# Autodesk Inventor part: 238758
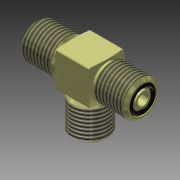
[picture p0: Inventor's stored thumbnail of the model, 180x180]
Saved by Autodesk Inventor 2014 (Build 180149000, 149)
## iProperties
Shininess: 20.0
Length Units: 11272
Angle Units: 11279
Time Units: 11290
Mass Units: 11286
Length Display Precision: 3
Angle Display Precision: 2
Company: Autodesk, Inc.
Created: 2002-06
Part Number: 238758
Material: Steel, Mild A-36
Description: Fitting; TE-C9C9C94-S
Document SubType Name: Modeling
Designer: Autodesk, Inc.
Density: 1 g/cm^3
Appearance: Yellow Zinc
Density: 0.0
Volumn: 0.0
Area: 0.0
PropertySet Name: Model Information
Control State: 0
Master: False
Checked Out: False
Last Check In By: JT
Last Check In Date: 2003-06-20
Title: Fitting; TE-C9C9C94-S
Author: Autodesk, Inc.
Comments: -
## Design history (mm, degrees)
sketch "Sketch1"
  geometry: L1 (-7.137, -7.137)-(7.137, -7.137); L2 (7.137, -7.137)-(7.137, 7.137); L3 (7.137, 7.137)-(-7.137, 7.137); L4 (-7.137, 7.137)-(-7.137, -7.137); L5 (-7.137, -7.137)-(7.137, 7.137); 2 further points
  constraints: 10 end point, 2 parallel, 1 coincident, 1 horizontal, 1 midpoint, 1 perpendicular
  dimensions: "d3" = 14.2748 distance of L2.end L3.end (= Body_Size); "d4" = 14.2748 distance of L3.end L1.start (= Body_Size)
extrude "Extrusion2" new body sketch "Sketch1" stored distance "d5" = 14.2748 (= Body_Size); taper "d6" = 0 deg
workplane "Work Plane1"
sketch "Sketch2"
  geometry: L1 (-7.137, 10.094)-(-7.137, 0) reference; L2 (7.137, 0)-(7.137, 10.094) reference; L3 (-7.137, 7.137)-(-6.616, 10.094); L4 (7.137, 7.137)-(6.616, 10.094); L5 (7.137, 7.137)-(-7.137, 7.137); L6 (-9.992, 0)-(9.992, 0) reference; L7 (-7.137, 10.094)-(-6.616, 10.094); L8 (6.616, 10.094)-(7.137, 10.094)
  constraints: 10 end point, 2 parallel, 2 point on line, 1 horizontal
  dimensions: "d7" = 14.2748 diameter of L5 L6 (= Body_Size); "d8" = 10 deg angle of L3 L1; "d9" = 10 deg angle of L2 L4 (= d8)
revolve "Revolution1" sketch "Sketch2" stored, may be unused: angle "d10" = 90 deg
fillet "Fillet1" dims "d11" = 0.762
sketch "Sketch3"
  geometry: L1 (-7.137, 7.137)-(-7.137, 0) reference; L2 (-7.137, 0)-(-7.137, -7.137) reference; L3 (0, 0)-(-46.922, 0); L4 (0, 0)-(49.071, 0); L5 (0, 0)-(0, -39.416); L6 (6.708, -7.137)-(-6.708, -7.137) reference; L7 (7.137, 0)-(7.137, 7.137) reference; L8 (7.137, -7.137)-(7.137, 0) reference; L9 (-7.137, 6.134)-(-7.899, 6.134); L10 (-7.899, 6.134)-(-8.909, 7.144); L11 (-8.909, 7.144)-(-20.58, 7.144); L12 (-20.58, 7.144)-(-21.59, 6.134); L13 (-21.59, 6.134)-(-21.59, 5.499); L14 (-21.59, 5.499)-(-20.244, 5.499); L15 (-20.244, 5.499)-(-20.244, 3.086); L16 (-20.244, 3.086)-(-21.59, 3.086); L17 (-21.59, 3.086)-(-21.59, 2.184); L18 (-21.59, 2.184)-(-7.137, 2.184); L19 (7.137, 6.134)-(7.899, 6.134); L20 (7.899, 6.134)-(8.909, 7.144); L21 (8.909, 7.144)-(20.58, 7.144); L22 (20.58, 7.144)-(21.59, 6.134); L23 (21.59, 6.134)-(21.59, 5.499); L24 (21.59, 5.499)-(20.244, 5.499); L25 (20.244, 5.499)-(20.244, 3.086); L26 (20.244, 3.086)-(21.59, 3.086); L27 (21.59, 3.086)-(21.59, 2.184); L28 (21.59, 2.184)-(7.137, 2.184); L29 (-6.134, -7.137)-(-6.134, -7.899); L30 (-6.134, -7.899)-(-7.144, -8.909); L31 (-7.144, -8.909)-(-7.144, -20.58); L32 (-7.144, -20.58)-(-6.134, -21.59); L33 (-6.134, -21.59)-(-5.499, -21.59); L34 (-5.499, -21.59)-(-5.499, -20.244); L35 (-5.499, -20.244)-(-3.086, -20.244); L36 (-3.086, -20.244)-(-3.086, -21.59); L37 (-3.086, -21.59)-(-2.184, -21.59); L38 (-2.184, -21.59)-(-2.184, -7.137); C1 r 0.787 at (-21.031, 4.61); C2 r 0.787 at (-4.61, -21.031); C3 r 0.787 at (21.031, 4.61)
  constraints: 66 end point, 14 perpendicular, 13 parallel, 6 point on line, 5 collinear, 3 centre point, 2 horizontal alignment, 1 vertical alignment
  dimensions: "d12" = 14.2875 diameter of L11 L3 (= Male2_Face_Seal_Thread_OD); "d13" = 12.2682 diameter of L12.end L3 (= Male2_Face_Seal_Lip); "d14" = 45 deg angle of L11 L12; "d15" = 10.9982 diameter of L14 L3 (= Male2_Face_Seal_Groove_Dia); "d16" = 1.3462 distance from line of L15.end L13; "d17" = 4.3688 diameter of L18 L3 (= Male2_Face_Seal_ID); "d18" = 2.413 distance between parallel lines of L16 L14; "d19" = 21.59 distance from line of L13 L3.start (= Male1_M); "d20" = 0.762 distance of L9.start L9.end (= Male2_Face_Seal_Undercut_Length_H); "d21" = 21.59 distance from line of L33 L3.start (= Male1_M); "d22" = 14.2875 diameter of L31 L5 (= Male2_Face_Seal_Thread_OD); "d23" = 45 deg angle of L31 L32; "d24" = 12.2682 diameter of L32.end L5 (= Male2_Face_Seal_Lip); "d25" = 0.762 distance of L29.start L29.end (= Male2_Face_Seal_Undercut_Length_H); "d26" = 10.9982 diameter of L34 L5 (= Male2_Face_Seal_Groove_Dia); "d27" = 2.413 distance between parallel lines of L36 L34; "d28" = 1.3462 distance between parallel lines of L35 L37; "d29" = 4.3688 diameter of L38 L5 (= Male2_Face_Seal_ID); "d30" = 21.59 distance from line of L27 L3.start (= Male2_M); "d31" = 14.2875 diameter of L21 L4 (= Male1_Face_Seal_Thread_OD); "d32" = 10.9982 diameter of L24 L4 (= Male1_Face_Seal_Groove_Dia); "d33" = 2.413 distance between parallel lines of L26 L24; "d34" = 1.3462 distance between parallel lines of L27 L25; "d35" = 0.762 distance of L19.start L19.end (= Male1_Face_Seal_Undercut_Length_H); "d36" = 45 deg angle of L21 L22; "d37" = 12.2682 diameter of L22.end L4 (= Male1_Face_Seal_Lip); "d38" = 4.3688 diameter of L28 L4 (= Male2_Face_Seal_ID); "d48" = 1.5748 diameter of C3 (= Male1_Face_Seal_Seal); "d49" = 1.5748 diameter of C1 (= Male2_Face_Seal_Seal); "d50" = 1.5748 diameter of C2 (= Male2_Face_Seal_Seal); "d53" = 21.0312 horizontal distance of L3.start C1.centre (computed from Male2_M, Male2_Face_Seal_Seal); "d54" = 21.0312 horizontal distance of L3.start C3.centre (computed from Male1_M, Male1_Face_Seal_Seal); "d55" = 21.0312 vertical distance of C2.centre L3.start (computed from Male2_M, Male2_Face_Seal_Seal); "d67" = 7.6454 dimension on C1 L3 (= Male2_Oring_Dia); "d68" = 7.6454 dimension on C3 L4 (= Male1_Oring_Dia); "d69" = 7.6454 dimension on C2 L5 (= Male2_Oring_Dia)
revolve "Male FS1" stored, may be unused: angle "d39" = 90 deg
revolve "Oring FS1" stored, may be unused: angle "d58" = 90 deg
revolve "Male FS2" stored, may be unused: angle "d40" = 90 deg
revolve "Oring FS2" stored, may be unused: angle "d59" = 90 deg
revolve "Male FS3" stored, may be unused: angle "d41" = 90 deg
revolve "Oring FS3" stored, may be unused: angle "d60" = 90 deg
feature "Male Thd FS1" dims "d42" = 25.4, "d43" = 0
feature "Male Thd FS2" dims "d44" = 25.4, "d45" = 0
feature "Male Thd FS3" dims "d46" = 25.4, "d47" = 0
sketch "Sketch4"
  geometry: C1 r 2.184 at (0, 0); 1 further point
  constraints: 1 centre point, 1 coincident
  dimensions: "d138" = 4.3688 diameter of C1 (derived)
extrude "FS1 Hole" cut sketch "Sketch4" distance "d61" = 7.1374 (= 0.5 x Body_Size); taper "d62" = 0 deg
sketch "Sketch5"
  geometry: C1 r 2.184 at (0, 0)
  constraints: 1 centre point
  dimensions: "d71" = 4.3688 diameter of C1 (= Male2_Face_Seal_ID)
extrude "FS2 Hole" cut sketch "Sketch5" distance "d63" = 7.1374 (= 0.5 x Body_Size); taper "d64" = 0 deg
sketch "Sketch6"
  geometry: C1 r 2.184 at (0, 0)
  constraints: 1 centre point
  dimensions: "d72" = 4.3688 diameter of C1 (= Male2_Face_Seal_ID)
extrude "FS3 Hole" cut sketch "Sketch6" distance "d65" = 7.1374 (= 0.5 x Body_Size); taper "d66" = 0 deg
sketch "Sketch7"
  geometry: L1 (6.708, -7.137)-(-6.708, -7.137) reference; L2 (0, 0)-(0, -79.032); L3 (-4.762, -7.137)-(-4.762, -25.933); L4 (-4.762, -25.933)-(-5.556, -25.933); L5 (-5.556, -25.933)-(-5.556, -27.178); L6 (-5.556, -27.178)-(-2.184, -27.178); L7 (-2.184, -27.178)-(-2.184, -7.137); L8 (-4.889, -25.679)-(-4.889, -19.653); L9 (-4.889, -19.653)-(-8.731, -19.653); L10 (-8.731, -19.653)-(-8.731, -34.385); L11 (-8.731, -34.385)-(-7.144, -34.385); L12 (-7.144, -34.385)-(-7.144, -27.432); L13 (-7.144, -27.432)-(-5.81, -27.432); L14 (-5.81, -27.432)-(-5.81, -25.679); L15 (-5.81, -25.679)-(-4.889, -25.679); L16 (7.137, -7.137)-(7.137, 0) reference; L17 (7.137, 0)-(7.137, 7.137) reference; L18 (7.137, 4.763)-(25.933, 4.763); L19 (25.933, 4.763)-(25.933, 5.556); L20 (25.933, 5.556)-(27.178, 5.556); L21 (27.178, 5.556)-(27.178, 2.184); L22 (27.178, 2.184)-(7.137, 2.184); L23 (25.679, 5.017)-(19.653, 5.017); L24 (19.653, 5.017)-(19.653, 8.731); L25 (19.653, 8.731)-(34.385, 8.731); L26 (34.385, 8.731)-(34.385, 7.144); L27 (34.385, 7.144)-(27.432, 7.144); L28 (27.432, 7.144)-(27.432, 5.81); L29 (27.432, 5.81)-(25.679, 5.81); L30 (25.679, 5.81)-(25.679, 5.017); L31 (0, 0)-(56.765, 0)
  constraints: 56 end point, 19 parallel, 9 perpendicular, 4 point on line
  dimensions: "d73" = 17.4625 diameter of L10 L2 (= Female1_Face_Seal_Hex_Size); "d74" = 14.2875 diameter of L12 L2 (= Female1_Face_Seal__Nut_Thread_ID); "d75" = 11.1125 diameter of L5 L2 (= Female1_Face_Seal_Lip_OD); "d76" = 11.6205 diameter of L14 L2 (computed from Female1_Face_Seal_Lip_OD); "d77" = 9.525 diameter of L3 L2 (= Female1_Face_Seal_Tube_OD); "d78" = 9.779 diameter of L8 L2 (computed from Female1_Face_Seal_Tube_OD); "d80" = 4.3688 diameter of L7 L2 (= Female1_Face_Seal_ID); "d81" = 27.178 distance from line of L6 L2.start (= Female1_Face_Seal_AAA); "d82" = 1.2446 distance between parallel lines of L6 L4; "d83" = 14.732 distance between parallel lines of L11 L9 (= Female1_Face_Seal_Nut_OAL); "d84" = 6.95325 distance between parallel lines of L11 L13 (= Female1_Face_Seal_Face_To_Nut); "d85" = 1.7526 distance between parallel lines of L15 L13; "d86" = 27.432 distance from line of L13 L2.start (computed from Female1_Face_Seal_AAA); "d119" = 17.4625 diameter of L25 L31 (derived); "d120" = 14.2875 diameter of L27 L31 (derived); "d121" = 11.1125 diameter of L20 L31 (derived); "d122" = 9.525 diameter of L18 L31 (derived); "d123" = 4.3688 diameter of L22 L31 (derived); "d124" = 10.033 diameter of L23 L31 (derived); "d125" = 11.6205 diameter of L29 L31 (derived); "d126" = 27.178 distance from line of L21 L2.start (derived); "d127" = 1.2446 distance between parallel lines of L19 L21; "d128" = 27.432 distance from line of L28 L2.start (derived); "d129" = 1.7526 distance from line of L23.start L28; "d131" = 14.732 distance between parallel lines of L24 L26 (derived); "d143" = 6.95325 distance between parallel lines of L26 L28 (derived)
revolve "Female2 Tube" stored, may be unused: angle "d87" = 90 deg
revolve "Female2 Hex" stored, may be unused: angle "d88" = 90 deg
sketch "Sketch8"
  geometry: L1 (0, 13.748)-(11.906, 6.874); L2 (11.906, 6.874)-(11.906, -6.874); L3 (11.906, -6.874)-(0, -13.748); L4 (0, -13.748)-(-11.906, -6.874); L5 (-11.906, -6.874)-(-11.906, 6.874); L6 (-11.906, 6.874)-(0, 13.748); C1 r 11.906 at (0, 0) reference; 1 further point
  constraints: 12 end point, 1 coincident, 1 tangent, 1 vertical alignment, 11 other
extrude "Female2 Hex Thk" join sketch "Sketch8" distance "d89" = 6.95325 (= Female1_Face_Seal_Face_To_Nut); taper "d90" = 0 deg
feature "Female2 Thd" [Male Thd FS] dims "d106" = 25.4, "d107" = 0
sketch "Sketch10"
  geometry: L1 (-34.385, 8.731)-(-34.385, 15.081); L2 (-34.385, 15.081)-(-32.684, 15.081); L3 (-32.684, 15.081)-(-34.385, 8.731); L4 (-27.432, 8.731)-(-27.432, 15.081); L5 (-27.432, 15.081)-(-29.133, 15.081); L6 (-29.133, 15.081)-(-27.432, 8.731); L7 (0, 0)-(-259.536, 0); L8 (0, 0)-(0, 22.08); L9 (-27.432, 8.731)-(-34.385, 8.731); L10 (-27.432, 8.731)-(-19.653, 8.731); L11 (-19.653, 8.731)-(-19.653, 5.524); L12 (-19.653, 5.524)-(-27.432, 8.731)
  constraints: 24 end point, 6 perpendicular, 2 collinear, 1 parallel, 1 vertical
  dimensions: "d108" = 27.432 distance between parallel lines of L4 L8 (derived); "d110" = 6.95325 distance between parallel lines of L1 L4 (derived); "d112" = 17.4625 diameter of L9 L7 (derived); "d113" = 15 deg angle of L3 L1; "d114" = 15 deg angle of L4 L6; "d115" = 30.1625 diameter of L2 L7 (derived); "d116" = 14.732 distance between parallel lines of L11 L1 (derived); "d117" = 11.049 diameter of L11.end L7 (derived)
revolve "Female2 Nut material Removal" sketch "Sketch10" stored, may be unused: angle "d118" = 90 deg
revolve "Female1 Tube" stored, may be unused: angle "d132" = 90 deg
revolve "Female1 Hex" stored, may be unused: angle "d133" = 90 deg
sketch "Sketch11"
  geometry: L1 (0, 10.082)-(8.731, 5.041); L2 (8.731, 5.041)-(8.731, -5.041); L3 (8.731, -5.041)-(0, -10.082); L4 (0, -10.082)-(-8.731, -5.041); L5 (-8.731, -5.041)-(-8.731, 5.041); L6 (-8.731, 5.041)-(0, 10.082); C1 r 8.731 at (0, 0) reference; 1 further point
  constraints: 12 end point, 1 coincident, 1 tangent, 1 vertical alignment, 11 other
extrude "Female1 Hex Thk" join sketch "Sketch11" distance "d134" = 6.95325 (derived); taper "d135" = 0 deg
feature "Female1 Thd" [Male Thd FS] dims "d136" = 25.4, "d137" = 0
sketch "Sketch12"
  geometry: L1 (0, 0)-(-173.385, 0); L2 (0, 0)-(0, 76.843); L3 (-27.432, -13.494)-(-27.432, -8.731); L4 (-27.432, -8.731)-(-28.708, -13.494); L5 (-28.708, -13.494)-(-27.432, -13.494); L6 (-34.385, -8.731)-(-33.109, -13.494); L7 (-33.109, -13.494)-(-34.385, -13.494); L8 (-34.385, -13.494)-(-34.385, -8.731); L9 (-27.432, -8.731)-(-19.653, -8.731); L10 (-19.653, -8.731)-(-19.653, -5.525); L11 (-19.653, -5.525)-(-27.432, -8.731); L12 (-34.385, -8.731)-(-27.432, -8.731); 1 further point
  constraints: 24 end point, 6 perpendicular, 2 collinear, 1 coincident, 1 horizontal, 1 parallel, 1 point on line
  dimensions: "d139" = 11.049 diameter of L10.end L1 (derived); "d140" = 17.4625 diameter of L12 L1 (derived); "d141" = 27.432 distance between parallel lines of L3 L2 (derived); "d142" = 6.95325 distance between parallel lines of L8 L3 (derived); "d144" = 26.9875 diameter of L7 L1 (derived); "d145" = 15 deg angle of L6 L8; "d146" = 15 deg angle of L3 L4; "d147" = 14.732 distance between parallel lines of L10 L8 (derived)
revolve "Female1 Nut material Removal" sketch "Sketch12" stored, may be unused: angle "d148" = 90 deg
body "Solid1"
other parameters: "Body_Size" = 14.2748 [user parameter; used in 7 equation terms], "Male1_Face_Seal_ID" = 4.3688 [user parameter], "Male1_Face_Seal_Groove_Dia" = 10.9982 [user parameter; used in 1 equation term], "Male1_Face_Seal_Lip" = 12.2682 [user parameter; used in 1 equation term], "Male1_Face_Seal_Thread_OD" = 14.2875 [user parameter; used in 1 equation term], "Male1_Oring_Dia" = 7.6454 [user parameter; used in 1 equation term], "Male1_M" = 21.59 [user parameter; used in 3 equation terms], "Male2_Face_Seal_ID" = 4.3688 [user parameter; used in 5 equation terms], "Male2_Face_Seal_Groove_Dia" = 10.9982 [user parameter; used in 2 equation terms], "Male2_Face_Seal_Lip" = 12.2682 [user parameter; used in 2 equation terms], "Male2_Face_Seal_Thread_OD" = 14.2875 [user parameter; used in 2 equation terms], "Male2_Oring_Dia" = 7.6454 [user parameter; used in 2 equation terms], "Male1_Face_Seal_Undercut_Length_H" = 0.762 [user parameter; used in 1 equation term], "Male2_Face_Seal_Undercut_Length_H" = 0.762 [user parameter; used in 2 equation terms], "Male2_M" = 21.59 [user parameter; used in 3 equation terms], "Male1_Face_Seal_Seal" = 1.5748 [user parameter; used in 2 equation terms], "Male2_Face_Seal_Seal" = 1.5748 [user parameter; used in 4 equation terms], "Female1_Face_Seal_Hex_Size" = 17.4625 [user parameter; used in 1 equation term], "Female1_Face_Seal__Nut_Thread_ID" = 14.2875 [user parameter; used in 1 equation term], "Female1_Face_Seal_Lip_OD" = 11.1125 [user parameter; used in 2 equation terms], "Female1_Face_Seal_Tube_OD" = 9.525 [user parameter; used in 2 equation terms], "Female1_Face_Seal_Nut_OAL" = 14.732 [user parameter; used in 1 equation term], "Female1_Face_Seal_Face_To_Nut" = 6.95325 [user parameter; used in 2 equation terms], "Female1_Face_Seal_ID" = 4.3688 [user parameter; used in 1 equation term], "Female1_Face_Seal_AAA" = 27.178 [user parameter; used in 2 equation terms]
